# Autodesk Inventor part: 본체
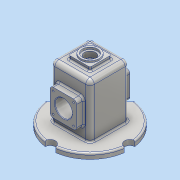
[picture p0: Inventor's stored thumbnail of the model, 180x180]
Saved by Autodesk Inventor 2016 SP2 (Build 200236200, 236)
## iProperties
Created: 2018-07
Part Number: 본체
Material: 알루미늄 6061
Document SubType Name: Modeling
Designer: Administrator
Density: 2.7 g/cm^3
Appearance: 알루미늄 - 평지
Mass: 909.368 g
Surface Area: 1016.32 cm^2
Volume: 336.803 cm^3
Author: Administrator
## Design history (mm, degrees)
sketch "스케치1"
  geometry: C1 r 75 at (0, 0); 1 further point
  constraints: 1 centre point, 1 coincident
  dimensions: "d0" = 150 diameter of C1
extrude "돌출1" new body sketch "스케치1" distance "d1" = 10; taper "d2" = 0 deg
sketch "스케치2"
  geometry: L1 (-37, -37)-(37, -37); L2 (37, -37)-(37, 37); L3 (37, 37)-(-37, 37); L4 (-37, 37)-(-37, -37); L5 (-37, -37)-(37, 37); L6 (37, -37)-(-37, 37); C1 r 75 at (0, 0) reference
  constraints: 12 end point, 2 midpoint, 2 parallel, 1 horizontal, 1 perpendicular
  dimensions: "d3" = 74 distance of L1.start L1.end; "d4" = 74 distance of L1.end L2.end
extrude "돌출2" join sketch "스케치2" distance "d5" = 100; taper "d6" = 0 deg
sketch "스케치3"
  geometry: L1 (-20, -20)-(20, -20); L2 (20, -20)-(20, 20); L3 (20, 20)-(-20, 20); L4 (-20, 20)-(-20, -20); L5 (-20, -20)-(20, 20); L6 (20, -20)-(-20, 20); 1 further point
  constraints: 12 end point, 2 midpoint, 2 parallel, 1 horizontal, 1 perpendicular
  dimensions: "d7" = 40 distance of L1.end L2.end; "d8" = 40 distance of L2.end L3.end
extrude "돌출3" join sketch "스케치3" distance "d9" = 7; taper "d10" = 0 deg
sketch "스케치4"
  geometry: C1 r 17.5 at (0, 0); 1 further point
  constraints: 1 centre point, 1 coincident
  dimensions: "d11" = 35 diameter of C1
extrude "돌출4" join sketch "스케치4" distance "d12" = 3; taper "d13" = 0 deg
sketch "스케치6"
  geometry: L1 (25, 30)-(-25, 30); L2 (-25, 30)-(-25, 80); L3 (-25, 80)-(25, 80); L4 (25, 80)-(25, 30); L5 (25, 30)-(-25, 80); L6 (-25, 30)-(25, 80); L7 (-75, 0)-(75, 0) reference; 4 further points
  constraints: 12 end point, 4 midpoint, 2 parallel, 1 horizontal, 1 perpendicular, 1 vertical alignment
  dimensions: "d16" = 55 distance from line of L7 point (0, 55); "d17" = 50 distance of L2.end L3.end; "d18" = 50 distance of L3.end L1.start
extrude "돌출5" join sketch "스케치6" stored distance "d19" = 100; taper "d20" = 0 deg
sketch "스케치7"
  geometry: L1 (32, 32)-(-32, 32); L2 (-32, 32)-(-32, -32); L3 (-32, -32)-(32, -32); L4 (32, -32)-(32, 32); L5 (32, 32)-(-32, -32); L6 (-32, 32)-(32, -32); C1 r 75 at (0, 0) reference
  constraints: 12 end point, 2 midpoint, 2 parallel, 1 horizontal, 1 perpendicular
  dimensions: "d21" = 64 distance of L2.end L3.end; "d22" = 64 distance of L3.end L1.start
extrude "돌출6" cut sketch "스케치7" distance "d23" = 105; taper "d24" = 0 deg
sketch "스케치9"
  geometry: C1 r 17.5 at (0, 0) reference
hole "구멍1" sketch "스케치9" at (0, 0) diameter "d28" = 21; stored, may be unused: countersink angle "d32" = 90 deg, drill point angle "d34" = 118 deg; dims "d29" = 6, "d30" = 28, "d31" = 4, "d33" = 8
sketch "스케치10"
  geometry: C1 r 10 at (75, 0); 1 further point
  constraints: 1 centre point, 1 horizontal alignment, 1 other
  dimensions: "d35" = 20 diameter of C1
extrude "돌출8" cut sketch "스케치10" stored distance "d36" = 105; taper "d37" = 0 deg
sketch "스케치12"
  geometry: L1 (25, 80)-(-25, 80) reference; L2 (-25, 80)-(-25, 30) reference; C1 r 16 at (0, 55); 3 further points
  constraints: 2 midpoint, 1 centre point, 1 horizontal alignment, 1 vertical alignment
  dimensions: "d45" = 32 diameter of C1
extrude "돌출9" cut sketch "스케치12" stored distance "d46" = 105; taper "d47" = 0 deg
sketch "스케치14"
  geometry: L1 (-50, 80)-(-50, 30) reference; L2 (-50, 55)-(50, 55); L3 (50, 30)-(50, 80) reference; L4 (-32, 80)-(-32, 55); L5 (-32, 55)-(-25, 55); L6 (-25, 55)-(-25, 77.452); L7 (-25, 77.452)-(-32, 80); L8 (-32, 0)-(-32, 105) reference; L9 (0, -24)-(0, 144) reference; L10 (32, 80)-(32, 55); L11 (32, 55)-(25, 55); L12 (25, 55)-(25, 77.452); L13 (25, 77.452)-(32, 80); 1 further point
  constraints: 18 end point, 4 symmetric about line, 2 collinear, 2 midpoint, 2 perpendicular, 1 vertical
  dimensions: "d48" = 7 distance between parallel lines of L4 L6; "d51" = 50 diameter of L4.start L2; "d52" = 110 deg angle of L8 L7
revolve "회전2" sketch "스케치14" stored, may be unused: angle "d53" = 90 deg
sketch "스케치15"
  geometry: C1 r 16 at (0, 0) reference; C2 r 16 at (0, 0); 1 further point
  constraints: 1 centre point, 1 coincident, 1 concentric
extrude "돌출10" cut sketch "스케치15" stored distance "d54" = 105; taper "d55" = 0 deg
fillet "모깎기1" dims "d56" = 3
fillet "모깎기2" dims "d57" = 6
chamfer "모따기1" distance "d58" = 1; stored, may be unused: second distance "d59" = 2, angle "d60" = 45 deg
fillet "모깎기3" dims "d61" = 3
fillet "모깎기4" dims "d62" = 3
fillet "모깎기5" dims "d63" = 8
fillet "모깎기6" dims "d64" = 8
fillet "모깎기7" dims "d65" = 3
fillet "모깎기8" dims "d66" = 3
fillet "모깎기9" dims "d67" = 3
fillet "모깎기10" dims "d68" = 3
sketch "스케치16"
  geometry: A1 r 6 centre (19, 36) between (19, 30) and (25, 36) reference; A2 r 6 centre (19, 74) between (25, 74) and (19, 80) reference; A3 r 6 centre (-19, 74) between (-19, 80) and (-25, 74) reference; A4 r 6 centre (-19, 36) between (-25, 36) and (-19, 30) reference; 1 further point
hole "구멍2" sketch "스케치16" at (19, 74), (19, 36), (-19, 36), (-19, 74) diameter "d69" = 3.242; stored, may be unused: countersink angle "d73" = 90 deg, drill point angle "d75" = 118 deg; dims "d70" = 8, "d71" = 28, "d72" = 4, "d74" = 10
sketch "스케치18"
  geometry: L1 (-8, 89)-(-8, 0) reference; L2 (11.5, -18)-(46.5, -18) reference; 2 further points
  constraints: 1 other
  dimensions: "d80" = 37 distance from line of L1 point (29, 12); "d81" = 30 distance from line of point (29, 12) L2
feature "엠보싱2" sketch "스케치18" dims "d1" = 10, "d82" = 0.5, "d83" = 0
node "솔리드1"
pattern_circular "원형 패턴1" dims angle "d39" = 360 deg
mirror "대칭1"
